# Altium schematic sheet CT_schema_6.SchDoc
size 277 x 170 mm
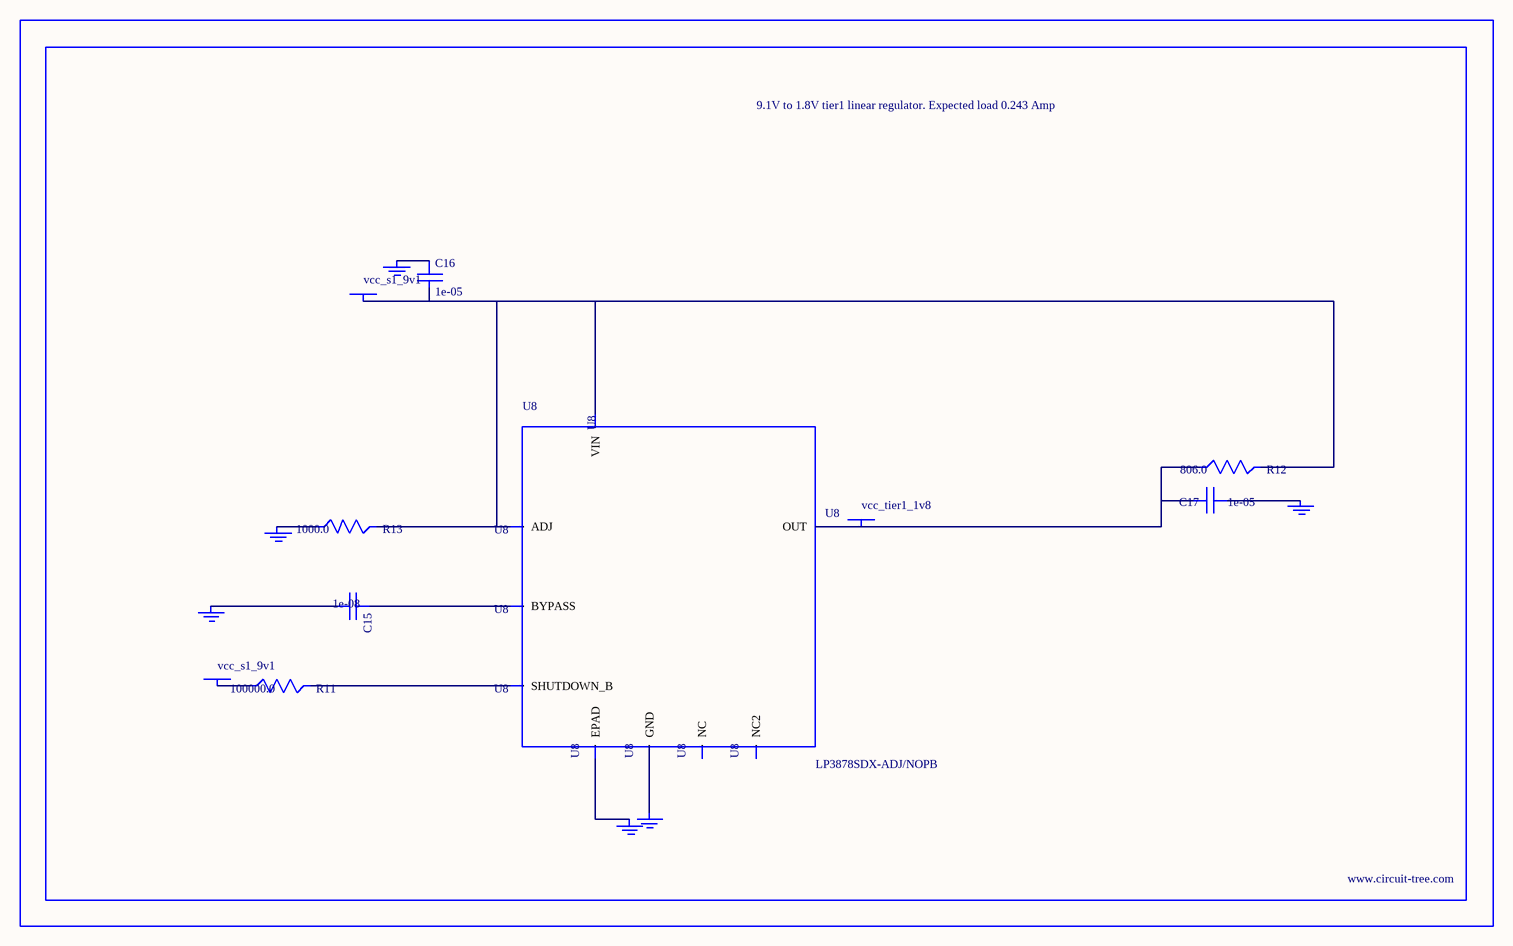
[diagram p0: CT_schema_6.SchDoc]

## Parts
BORDER5  (no value)
C15  1e-08  [C0402]
C16  1e-05  [C1206]
C17  1e-05  [C0805]
GND_INSTANCE_5_0  (no value)
GND_INSTANCE_5_1  (no value)
GND_INSTANCE_5_2  (no value)
GND_INSTANCE_5_3  (no value)
GND_INSTANCE_5_4  (no value)
GND_INSTANCE_5_5  (no value)
POWER_INSTANCE_5_0  vcc_s1_9v1
POWER_INSTANCE_5_1  vcc_s1_9v1
POWER_INSTANCE_5_2  vcc_tier1_1v8
R11  100000.0  [R0603]
R12  806.0  [R0603]
R13  1000.0  [R0603]
U8  LP3878SDX-ADJ/NOPB  [WSON-8]

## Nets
NetC15_1: C15.1 U8.1(BYPASS)
NetC15_2: C15.2 GND_INSTANCE_5_0.0(GND)
NetC16_1: C16.1 GND_INSTANCE_5_1.0(GND)
NetC16_2: C16.2 POWER_INSTANCE_5_0.0(PWR) R12.2 R13.2 U8.4(VIN) U8.6(ADJ)
NetC17_1: C17.1 GND_INSTANCE_5_2.0(GND)
NetC17_2: C17.2 POWER_INSTANCE_5_2.0(PWR) R12.1 U8.5(OUT)
NetGND_INSTANCE_5_3_0: GND_INSTANCE_5_3.0(GND) R13.1
NetGND_INSTANCE_5_4_0: GND_INSTANCE_5_4.0(GND) U8.PAD(EPAD)
NetGND_INSTANCE_5_5_0: GND_INSTANCE_5_5.0(GND) U8.3(GND)
NetPOWER_INSTANCE_5_1_0: POWER_INSTANCE_5_1.0(PWR) R11.1
NetR11_2: R11.2 U8.8(SHUTDOWN_B)

Not connected (* = marked no-connect by the designer): U8 2(NC) 7(NC2)

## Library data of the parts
BORDER5 = BORDER_PAGE5
C15 = C0402C103K3RAC
C16 = C1206C106K3RACTU
C17 = GRM219R60J106ME19D
GND_INSTANCE_5_0-GND_INSTANCE_5_5 = GND
POWER_INSTANCE_5_0-POWER_INSTANCE_5_2 = PWR
R11 = RC0603JR-07100KL
R12 = ERJ-3EKF8060V
R13 = RC0603JR-071KL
